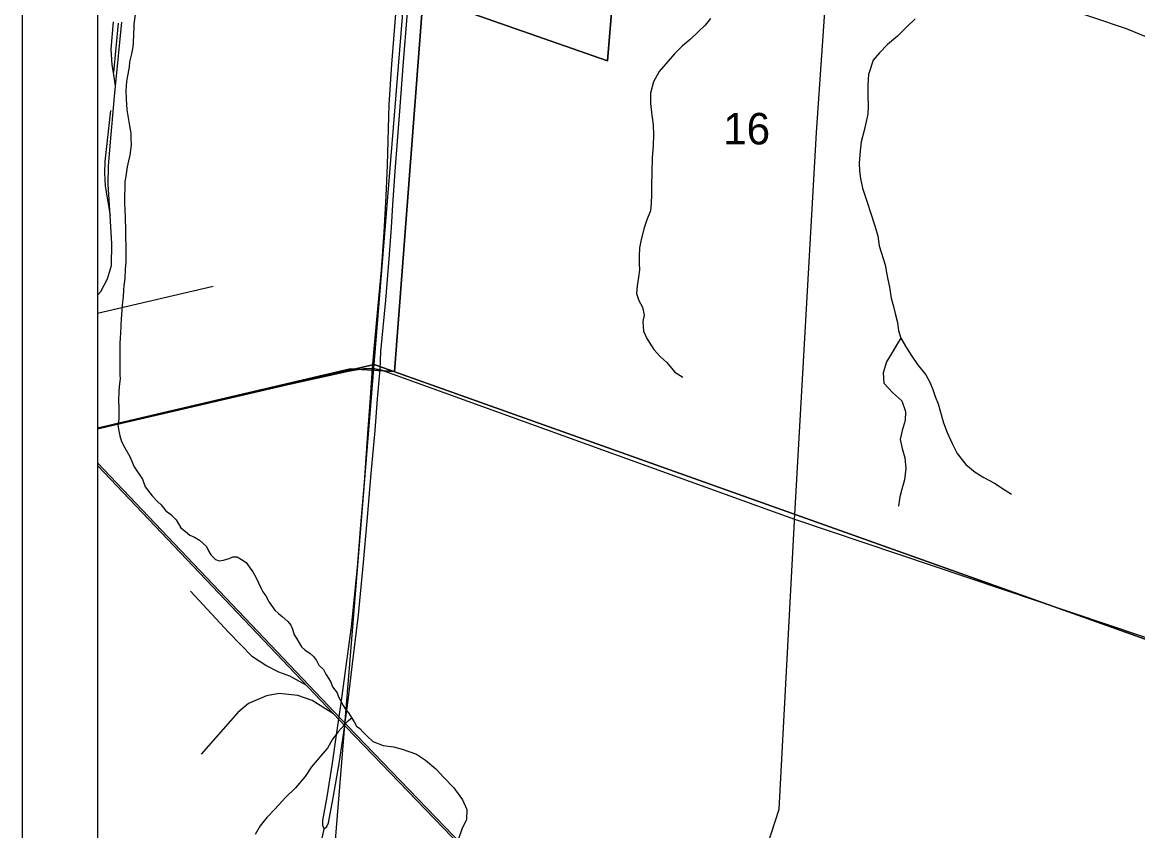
# Model space of a CAD drawing. Extents: x 0 to 34, y 0 to 22.
# Drawn here: x 2 to 3.482, y 17.132 to 18.207 of the extents above; entities that cross this region are included whole.
import ezdxf

# ---------------------------------------------------------------- set-up
doc = ezdxf.new("R2010")
doc.units = 0
for name, color, linetype in [('Default', 7, 'Continuous'), ('GM_X_City_Street', 7, 'Continuous'), ('GM_X_County_Road', 7, 'Continuous'), ('GM_X_Minor_River', 7, 'Continuous'), ('GM_X_Rail_Line', 7, 'Continuous'), ('GM_X_Section', 7, 'Continuous'), ('GM_X_Section_Text', 7, 'Continuous'), ('GM_X_State_Route', 7, 'Continuous'), ('GM_X_Township_Road', 7, 'Continuous'), ('SH_Cut_Line', 7, 'Continuous'), ('SH_Data', 7, 'Continuous')]:
    doc.layers.add(name, color=color, linetype=linetype)

msp = doc.modelspace()

# ---------------------------------------------------------------- linework, layer by layer
at = {"layer": 'Default'}
for points in [[(2.4795, 18.801), (2.1, 18.6881), (2.1, 17.6666), (2.4678, 17.7524), (2.5533, 18.801)], [(2.1, 18.801), (2.1, 17.6674), (2.4362, 17.7466), (2.4945, 17.7428), (2.5327, 18.2417), (2.7778, 18.1558), (2.8131, 18.5849), (2.8804, 18.6491), (2.977, 18.6303), (3.0953, 18.5833), (3.1049, 18.7791), (3.0479, 18.7812), (3.0475, 18.801)], [(2.8131, 18.5849), (2.7778, 18.1558), (2.5327, 18.2417), (2.4945, 17.7428), (2.4362, 17.7466), (2.1, 17.6674), (2.1, 15.6423), (2.3082, 15.6745), (2.5606, 15.599), (3.3845, 15.362), (3.4491, 16.1969), (3.7972, 16.2327), (3.8103, 16.3888), (3.7967, 16.3876), (3.8259, 16.7634), (3.5062, 16.7356), (3.5564, 17.3695), (3.6226, 18.1301), (3.6176, 18.1479), (3.628, 18.1636), (3.6366, 18.1888), (3.6479, 18.2377)]]:
    msp.add_lwpolyline(points, dxfattribs=at)
msp.add_lwpolyline([(2.1, 17.6666), (2.1, 16.6619), (2.3835, 16.7168), (2.4678, 17.7524)], close=True, dxfattribs=at)
at = {"layer": 'GM_X_City_Street'}
msp.add_lwpolyline([(2.8276, 16.5443), (2.8934, 16.7739), (2.923, 16.8761), (2.9901, 17.1121), (3.006, 17.1613), (3.0262, 17.5439), (3.0263, 17.5466), (3.0267, 17.5529), (3.0555, 18.0608), (3.0708, 18.2789), (3.0961, 18.5247), (3.1069, 18.6844), (3.1163, 18.801)], dxfattribs=at)
at = {"layer": 'GM_X_County_Road'}
msp.add_line((2.4653, 17.7473), (2.4755, 17.7454), dxfattribs=at)
for points in [[(3.0718, 18.2788), (3.1658, 18.2699), (3.2524, 18.2573), (3.3817, 18.2277), (3.4672, 18.1987), (3.5902, 18.1482), (3.6107, 18.1365), (3.6157, 18.1336), (3.627, 18.1271)], [(2.1, 17.6673), (2.1576, 17.6811), (2.261, 17.7051), (2.4334, 17.7433), (2.4537, 17.747), (2.4653, 17.7473)], [(2.4755, 17.7454), (2.9932, 17.5584), (3.0263, 17.5466), (3.4872, 17.3916), (3.5483, 17.37), (3.5629, 17.3674)]]:
    msp.add_lwpolyline(points, dxfattribs=at)
at = {"layer": 'GM_X_Minor_River'}
for points in [[(2.1499, 18.2174), (2.1484, 18.2045), (2.1483, 18.1984), (2.1477, 18.1927), (2.1474, 18.1787), (2.1464, 18.1719), (2.1451, 18.1654), (2.1425, 18.1545), (2.142, 18.1476), (2.1393, 18.1336), (2.1384, 18.1283), (2.1377, 18.1162), (2.1382, 18.1055), (2.1389, 18.0906), (2.1426, 18.0696), (2.1442, 18.0597), (2.1444, 18.0536), (2.1445, 18.0437), (2.1427, 18.0304), (2.1413, 18.0228), (2.1392, 18.0149)], [(2.9147, 18.2122), (2.9076, 18.2033), (2.8982, 18.1944), (2.8877, 18.1841), (2.8768, 18.1753), (2.8666, 18.165), (2.8552, 18.152), (2.8465, 18.1417), (2.8389, 18.1278), (2.835, 18.1131), (2.835, 18.0991), (2.8368, 18.0838), (2.8383, 18.0708), (2.8387, 18.0575), (2.8383, 18.0435), (2.837, 18.0268), (2.8365, 18.0085), (2.8363, 17.9892), (2.8364, 17.9778), (2.8357, 17.9667), (2.835, 17.9565), (2.8301, 17.9445), (2.8263, 17.934), (2.8224, 17.9185), (2.8202, 17.9075), (2.8199, 17.8961), (2.82, 17.8866), (2.8201, 17.8779), (2.8191, 17.8684), (2.8172, 17.8567), (2.8161, 17.8465), (2.8193, 17.8372), (2.8244, 17.8284), (2.8263, 17.818), (2.8249, 17.8093), (2.8257, 17.7964), (2.83, 17.7867), (2.8394, 17.772), (2.8479, 17.763), (2.8568, 17.7548), (2.8674, 17.7419), (2.8779, 17.7355)], [(3.1868, 18.2116), (3.1751, 18.2005), (3.163, 18.1886), (3.1499, 18.1775), (3.1393, 18.1664), (3.1307, 18.1567), (3.1245, 18.1379), (3.1238, 18.1242), (3.1238, 18.1098), (3.1243, 18.0961), (3.1236, 18.0851), (3.1214, 18.0753), (3.1189, 18.0635), (3.1151, 18.0484), (3.1136, 18.0363), (3.1121, 18.02), (3.1126, 18.0097), (3.1138, 17.9994), (3.1166, 17.9868), (3.1197, 17.9772), (3.1233, 17.9665), (3.1271, 17.9542), (3.1324, 17.9381), (3.137, 17.9232), (3.1389, 17.9098), (3.1467, 17.8845), (3.1487, 17.8746), (3.1504, 17.865), (3.1524, 17.8551), (3.1547, 17.8402), (3.1578, 17.8295), (3.1602, 17.8199), (3.163, 17.8081), (3.1646, 17.7974), (3.1678, 17.7874), (3.175, 17.7743), (3.1813, 17.7647), (3.1897, 17.7523), (3.2007, 17.7387), (3.2062, 17.7287), (3.2101, 17.7191), (3.2133, 17.7095), (3.2172, 17.6999), (3.2204, 17.6888), (3.2242, 17.6746), (3.2292, 17.6616), (3.236, 17.6473), (3.2425, 17.6338), (3.254, 17.6195), (3.2662, 17.6089), (3.2778, 17.6018), (3.2921, 17.5946), (3.3048, 17.5859), (3.3149, 17.5799)], [(2.1392, 18.0149), (2.1378, 18.0024), (2.1364, 17.9952), (2.1362, 17.9853), (2.1356, 17.9781), (2.1357, 17.9667), (2.1362, 17.9579), (2.1367, 17.9473), (2.137, 17.9313), (2.1371, 17.9218), (2.1376, 17.9092), (2.1377, 17.9012), (2.1374, 17.8886), (2.1368, 17.8788), (2.1361, 17.8666), (2.1351, 17.8571), (2.1345, 17.8511), (2.1339, 17.8427), (2.1328, 17.8309), (2.1323, 17.8237), (2.1316, 17.8135), (2.131, 17.8047), (2.1303, 17.793), (2.1302, 17.7884), (2.1296, 17.7793), (2.1297, 17.769), (2.1294, 17.7587), (2.1295, 17.7496), (2.1296, 17.7386), (2.1299, 17.7332), (2.1288, 17.723), (2.1283, 17.7162), (2.128, 17.704), (2.1285, 17.6956), (2.1281, 17.6793), (2.1271, 17.6724), (2.1277, 17.6663), (2.1294, 17.6572), (2.1319, 17.6499), (2.1362, 17.6414), (2.1427, 17.6298), (2.1485, 17.6163), (2.1598, 17.5997), (2.1634, 17.5897), (2.1726, 17.5777), (2.18, 17.5695), (2.1844, 17.5656), (2.1907, 17.5578), (2.1974, 17.5527), (2.2044, 17.5457), (2.2106, 17.5352), (2.217, 17.5301), (2.2225, 17.5254), (2.2289, 17.5226), (2.2357, 17.5186), (2.2446, 17.5104), (2.2475, 17.5046), (2.2504, 17.4992), (2.2567, 17.4929), (2.2616, 17.4913), (2.2673, 17.4923), (2.275, 17.4944), (2.2796, 17.4965), (2.2857, 17.4964), (2.2913, 17.4932), (2.2973, 17.4892), (2.3017, 17.4834), (2.3065, 17.4768), (2.3105, 17.4695), (2.3173, 17.4545), (2.3195, 17.4499), (2.3235, 17.4448), (2.3279, 17.4363), (2.3312, 17.4317), (2.3356, 17.4255), (2.3404, 17.4212), (2.3452, 17.4172), (2.353, 17.4106), (2.3571, 17.4055), (2.3592, 17.4005), (2.3613, 17.3929), (2.365, 17.3874), (2.3679, 17.382), (2.3712, 17.377), (2.3756, 17.3727), (2.3824, 17.368), (2.3872, 17.364), (2.3912, 17.3586), (2.3941, 17.3524), (2.4001, 17.3466), (2.4033, 17.3404), (2.4073, 17.3342), (2.4106, 17.3292), (2.4124, 17.3238), (2.4183, 17.3157), (2.42, 17.3111), (2.4229, 17.3057), (2.4266, 17.2991), (2.4291, 17.2945), (2.4335, 17.289), (2.4379, 17.2821)], [(3.1678, 17.7874), (3.1634, 17.7811), (3.1559, 17.7683), (3.1487, 17.7556), (3.1442, 17.7413), (3.145, 17.7276), (3.1568, 17.7147), (3.1691, 17.7038), (3.174, 17.6896), (3.1734, 17.6778), (3.1692, 17.6646), (3.1667, 17.6525), (3.1694, 17.6406), (3.1729, 17.628), (3.1744, 17.6139), (3.1725, 17.5988), (3.1688, 17.5863), (3.1663, 17.5765), (3.1644, 17.564)], [(2.4379, 17.2821), (2.4318, 17.277), (2.4196, 17.264), (2.4122, 17.254), (2.4054, 17.2423), (2.3967, 17.2319), (2.3842, 17.2174), (2.3758, 17.2047), (2.3633, 17.1894), (2.35, 17.1765), (2.3359, 17.1616), (2.3249, 17.1501), (2.3163, 17.139), (2.3095, 17.1273)], [(2.4379, 17.2821), (2.4412, 17.277), (2.4441, 17.2716), (2.4486, 17.2681), (2.453, 17.2634), (2.4582, 17.258)], [(2.4582, 17.258), (2.466, 17.251), (2.4796, 17.2457), (2.4932, 17.2438), (2.5049, 17.2408), (2.5237, 17.2342), (2.5357, 17.2263), (2.5494, 17.2149), (2.5601, 17.2032), (2.5734, 17.1895), (2.5852, 17.1736), (2.5909, 17.1608), (2.5905, 17.1475), (2.5841, 17.1344), (2.5799, 17.1216), (2.5766, 17.1095), (2.5796, 17.0964), (2.5839, 17.0861), (2.5893, 17.0741)]]:
    msp.add_lwpolyline(points, dxfattribs=at)
at = {"layer": 'GM_X_Rail_Line'}
for p, q in [((2.1272, 18.2061), (2.121, 18.1403)), ((2.124, 18.1223), (2.1321, 18.2071)), ((2.124, 18.1223), (2.121, 18.1403)), ((2.1, 17.8203), (2.2535, 17.8562))]:
    msp.add_line(p, q, dxfattribs=at)
for points in [[(2.121, 18.1403), (2.1193, 18.1508), (2.118, 18.1712), (2.121, 18.2077)], [(2.1166, 17.9505), (2.1141, 17.9914), (2.1147, 18.016), (2.1167, 18.0427), (2.1226, 18.1084), (2.124, 18.1223)], [(2.1174, 18.0897), (2.1098, 18.022), (2.1091, 18.0068), (2.1101, 17.9894), (2.1166, 17.9505)], [(2.1, 17.8443), (2.1045, 17.8493), (2.1134, 17.8661), (2.1187, 17.8839), (2.119, 17.9128), (2.1166, 17.9505)], [(4.2039, 15.4164), (3.7439, 15.8967), (3.3428, 16.3169), (3.153, 16.5162), (2.8982, 16.7851), (2.7005, 16.9902), (2.596, 17.1019), (2.4324, 17.2718), (2.1, 17.6214)], [(4.2011, 15.4158), (3.7421, 15.895), (3.341, 16.3152), (3.1512, 16.5145), (2.8964, 16.7834), (2.6987, 16.9885), (2.5942, 17.1001), (2.4306, 17.27), (2.1, 17.6178)], [(2.3774, 17.326), (2.3554, 17.338), (2.341, 17.3434), (2.3235, 17.3522), (2.3061, 17.3637), (2.2739, 17.3966), (2.2236, 17.4511)], [(2.4137, 17.2877), (2.3853, 17.3055), (2.3663, 17.3121), (2.3413, 17.315), (2.3245, 17.3117), (2.3005, 17.3015), (2.2864, 17.2897), (2.2377, 17.2341)]]:
    msp.add_lwpolyline(points, dxfattribs=at)
at = {"layer": 'GM_X_Section'}
msp.add_lwpolyline([(2.6081, 18.801), (3.6423, 18.3609), (3.5572, 17.3639), (2.4678, 17.7524), (2.5533, 18.801)], dxfattribs=at)
msp.add_lwpolyline([(2.4678, 17.7524), (3.5572, 17.3639), (3.4704, 16.3589), (2.3835, 16.7168)], close=True, dxfattribs=at)
at = {"layer": 'GM_X_State_Route'}
for points in [[(2.4653, 17.7473), (2.4678, 17.773), (2.473, 17.8306), (2.4772, 17.8778), (2.4811, 17.9282), (2.4838, 17.9759), (2.4853, 18.0171), (2.4877, 18.0978), (2.4912, 18.1516), (2.4969, 18.2236), (2.5, 18.2627), (2.5025, 18.2962)], [(2.4925, 17.9643), (2.4956, 18.0091), (2.5018, 18.089), (2.5063, 18.1486), (2.5121, 18.2206), (2.5139, 18.2436)], [(2.4013, 17.1348), (2.4049, 17.1381), (2.4069, 17.1429), (2.413, 17.176), (2.4211, 17.2219), (2.4265, 17.2572), (2.4333, 17.3056), (2.439, 17.3542), (2.4467, 17.4195), (2.4534, 17.4891), (2.4583, 17.5439), (2.4636, 17.6074), (2.469, 17.6646), (2.4721, 17.7065), (2.4755, 17.7454), (2.4766, 17.7696), (2.483, 17.8378), (2.4875, 17.8929), (2.4905, 17.9345), (2.4925, 17.9643)], [(2.4013, 17.1348), (2.3994, 17.1392), (2.3995, 17.1461), (2.405, 17.1773), (2.4122, 17.2221), (2.4175, 17.2598), (2.4239, 17.302), (2.4292, 17.3413), (2.4377, 17.4036), (2.4455, 17.4823), (2.4501, 17.5391), (2.4546, 17.5955), (2.4591, 17.6603), (2.4626, 17.708), (2.4653, 17.7473)], [(2.3321, 16.8678), (2.3446, 16.9107), (2.3575, 16.955), (2.3688, 16.9983), (2.3802, 17.0408), (2.3901, 17.0825), (2.4013, 17.1348)]]:
    msp.add_lwpolyline(points, dxfattribs=at)
at = {"layer": 'GM_X_Township_Road'}
msp.add_lwpolyline([(2.1, 18.801), (2.1, 15.6427), (2.3082, 15.6745), (2.4145, 15.6427), (2.5606, 15.599), (3.3455, 15.3733), (3.3845, 15.362), (3.4311, 15.9332), (3.4604, 16.2167), (3.4676, 16.3592), (3.5285, 17.1302), (3.548, 17.3706), (3.5984, 17.9897), (3.6087, 18.1157), (3.6104, 18.137), (3.6645, 18.801)], dxfattribs=at)
at = {"layer": 'SH_Cut_Line'}
msp.add_lwpolyline([(2.1, 18.801), (2.1, 15.6427), (2.3082, 15.6745), (2.4145, 15.6427), (2.5606, 15.599), (3.3455, 15.3733), (3.3845, 15.362), (3.4976, 15.3675)], dxfattribs=at)
at = {"layer": 'SH_Data'}
for p, q in [((2, 21), (2, 14)), ((2.1, 20.9), (2.1, 14.1))]:
    msp.add_line(p, q, dxfattribs=at)

# ---------------------------------------------------------------- texts
at = {"layer": 'GM_X_Section_Text'}
msp.add_text('16', height=0.04186, rotation=0, dxfattribs=at).set_placement((2.9316, 18.0448))

doc.saveas('drawing.dxf')
